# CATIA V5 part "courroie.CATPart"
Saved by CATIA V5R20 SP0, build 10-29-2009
Part number: courroie
Bounding box of the stored display mesh (mm): x -49.806 to 417.061, y -74.817 to 74.817, z 0 to 10
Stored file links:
  C:\Users\halimelbaba\Documents\cmv\final\courroie.CATPart
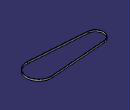
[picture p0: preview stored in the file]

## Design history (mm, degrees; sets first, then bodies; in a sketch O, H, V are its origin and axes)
Body1 (main body)
  Sketch1 on xy-plane, origin (0, 0, 0), H (1, 0, 0), V (0, 1, 0)
    arc A1 centre (0, 0) radius 50 from (-3.6523, 49.8664) to (-3.6523, -49.8664) ccw
    arc A2 centre (342.252, 0) radius 75 from (336.7736, -74.7996) to (336.7736, 74.7996) ccw
    point P1 (342.252, 0)
    point P2 (306.4633, 65.9103)
    line L1 (-3.6523, 49.8664) -> (336.7736, 74.7996)
    line L2 (-3.6523, -49.8664) -> (336.7736, -74.7996)
    radius A1 = 50
    distance P1 O = 342.252
    radius A2 = 75
    coincidence: P1 H, P2 A2
    tangency: L2 A1, L2 A2, L1 A2, L1 A1
  Pad1: profile Sketch1, direction (0, 0, 1), length 10, thin wall 2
